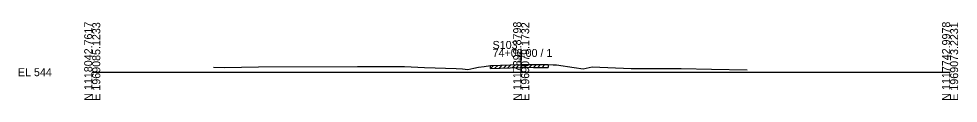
# Model space of a CAD drawing. Extents: x 974 to 1303, y 990 to 14518.
# Drawn here: x 974.3 to 1302.8, y 13490.3 to 13517.5 of the extents above; entities that cross this region are included whole.
import ezdxf

# ---------------------------------------------------------------- set-up
doc = ezdxf.new("R2010")
doc.units = 0
for name, color, linetype in [('Level 10', 7, 'Continuous'), ('Level 60', 7, 'Continuous'), ('Level 61', 7, 'Continuous'), ('Level 63', 7, 'Continuous')]:
    doc.layers.add(name, color=color, linetype=linetype)

msp = doc.modelspace()

# ---------------------------------------------------------------- linework, layer by layer
at = {"layer": 'Level 60'}
for p, q in [((1150, 13502.68), (1151.05, 13502.71)), ((1151.05, 13502.71), (1154.31, 13502.68)), ((1042.43, 13501.81), (1046.24, 13501.59)), ((1046.24, 13501.59), (1058.12, 13501.89)), ((1058.12, 13501.89), (1092.77, 13501.99)), ((1092.77, 13501.99), (1109.25, 13501.96)), ((1109.25, 13501.96), (1116.19, 13501.7)), ((1116.19, 13501.7), (1127.25, 13501.29)), ((1127.25, 13501.29), (1129.49, 13501.13)), ((1129.49, 13501.13), (1131.36, 13500.95)), ((1131.36, 13500.95), (1133.44, 13501.38)), ((1133.44, 13501.38), (1135.07, 13501.75)), ((1135.07, 13501.75), (1137.04, 13502.02)), ((1137.04, 13502.02), (1139.31, 13502.31)), ((1139.31, 13502.31), (1146.17, 13502.54)), ((1146.17, 13502.54), (1150, 13502.68)), ((1154.31, 13502.68), (1159.45, 13502.66)), ((1159.45, 13502.66), (1161.24, 13502.6)), ((1161.24, 13502.6), (1162.33, 13502.57)), ((1162.33, 13502.57), (1168.54, 13501.68)), ((1168.54, 13501.68), (1171.68, 13501.23)), ((1171.68, 13501.23), (1173.75, 13501.68)), ((1173.75, 13501.68), (1174.83, 13501.87)), ((1174.83, 13501.87), (1188.43, 13501.32)), ((1188.43, 13501.32), (1205.95, 13501.27)), ((1205.95, 13501.27), (1216.58, 13501.06)), ((1216.58, 13501.06), (1229.02, 13500.83))]:
    msp.add_line(p, q, dxfattribs=at)
at = {"layer": 'Level 61'}
for p, q in [((1149.81, 13501.67), (1150.85, 13502.71)), ((1151.31, 13501.71), (1152.3, 13502.7)), ((1139.31, 13501.31), (1140.35, 13502.35)), ((1139.31, 13501.31), (1139.31, 13502.31)), ((1139.31, 13501.31), (1146.17, 13501.54)), ((1140.81, 13501.36), (1141.85, 13502.4)), ((1142.31, 13501.41), (1143.35, 13502.45)), ((1143.81, 13501.46), (1144.85, 13502.5)), ((1145.31, 13501.51), (1146.35, 13502.55)), ((1146.17, 13501.54), (1150, 13501.68)), ((1146.81, 13501.57), (1147.85, 13502.6)), ((1148.31, 13501.62), (1149.35, 13502.65)), ((1150, 13501.68), (1151.05, 13501.71)), ((1151.05, 13501.71), (1154.31, 13501.68)), ((1152.81, 13501.7), (1153.8, 13502.69)), ((1154.31, 13501.68), (1155.31, 13502.68)), ((1154.31, 13501.68), (1159.45, 13501.66)), ((1155.81, 13501.67), (1156.81, 13502.67)), ((1157.31, 13501.67), (1158.31, 13502.66)), ((1159.45, 13502.66), (1159.45, 13501.66)), ((1159.45, 13501.66), (1159.45, 13501.66))]:
    msp.add_line(p, q, dxfattribs=at)
at = {"layer": 'Level 63'}
for p, q in [((1150, 13500), (1150, 13508.14)), ((1000, 13500), (1150, 13500)), ((1150, 13500), (1300, 13500))]:
    msp.add_line(p, q, dxfattribs=at)

# ---------------------------------------------------------------- texts
at = {"layer": 'Level 10'}
msp.add_text('546.68', height=0.9, rotation=90, dxfattribs=at).set_placement((1149.95, 13503.18))
at = {"layer": 'Level 63'}
for s, p in [('N 1118042.7617', (1000, 13490)), ('E 1969085.1233', (1002.8, 13490)), ('N 1117892.8798', (1150, 13490)), ('E 1969079.1732', (1152.8, 13490)), ('N 1117742.9978', (1300, 13490)), ('E 1969073.2231', (1302.8, 13490))]:
    msp.add_text(s, height=2.8, rotation=90, dxfattribs=at).set_placement(p)
for s, p in [('S103', (1140, 13508.14)), ('74+00.00 / 1', (1140, 13505.34)), ('EL 544', (974, 13498.6))]:
    msp.add_text(s, height=2.8, dxfattribs=at).set_placement(p)

doc.saveas('drawing.dxf')
